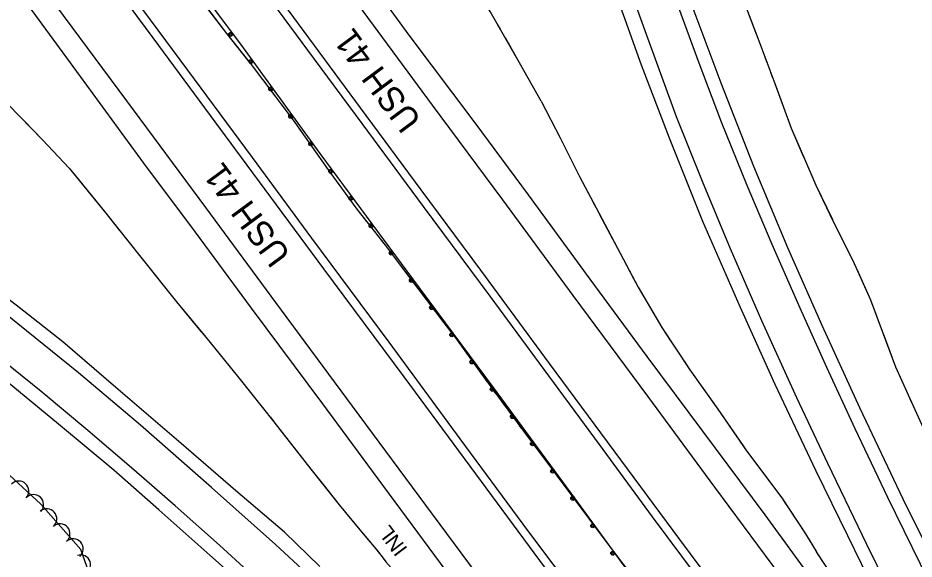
# Model space of a CAD drawing. Extents: x 353423 to 364002, y 127000 to 201942.
# Drawn here: x 359462 to 359820.6, y 132026.4 to 132242.7 of the extents above; entities that cross this region are included whole.
import ezdxf

# ---------------------------------------------------------------- set-up
doc = ezdxf.new("R2010")
doc.units = 0
for name, color, linetype in [('E_DTM_SlopeBottom', 7, 'Continuous'), ('E_DTM_SlopeTop', 7, 'Continuous'), ('E_FEN_Generic', 7, 'Continuous'), ('E_MISCPROP', 7, 'Continuous'), ('E_RW_IP', 7, 'Continuous'), ('E_STRUCT_WingWall', 7, 'Continuous')]:
    doc.layers.add(name, color=color, linetype=linetype)

msp = doc.modelspace()

# ---------------------------------------------------------------- linework, layer by layer
at = {"layer": 'E_DTM_SlopeTop'}
for points in [[(359296.04, 132656.2), (359327.36, 132613.62), (359357.21, 132573.34), (359387.83, 132532.04), (359420.96, 132487.16), (359453.44, 132443.29), (359480.05, 132407.27), (359517.09, 132357.33), (359543.42, 132321.88), (359571.35, 132284.17), (359599.99, 132245.46), (359627.75, 132207.82), (359655.85, 132169.95), (359684.1, 132131.8), (359713.89, 132091.57), (359740.72, 132055.1), (359769.42, 132016.5), (359798.55, 131977.39), (359823.57, 131943.56), (359849.91, 131908.1), (359879.42, 131867.94), (359910.1, 131826.75), (359934.24, 131793.99), (359949.98, 131772.5)], [(359894.52, 131723.73), (359866.32, 131761.93), (359834.77, 131804.35), (359801.8, 131849.06), (359771.18, 131890.36), (359741.61, 131930.36), (359706.83, 131977.37), (359677.25, 132017.15), (359645.21, 132060.41), (359616.57, 132099.29), (359584.47, 132142.49), (359551.44, 132186.98), (359516.16, 132234.78), (359477.26, 132287.18), (359438.91, 132339.08), (359394.26, 132399.62), (359356.73, 132450.28), (359318.1, 132502.23), (359283.37, 132549.19), (359243.7, 132602.83), (359207.65, 132651.41)], [(359559.38, 132644.69), (359570.47, 132614.62), (359581.22, 132584.68), (359594.59, 132548.52), (359605.61, 132517.85), (359617.82, 132483.54), (359630.69, 132448.17), (359643.78, 132412.18), (359657.78, 132373.3), (359671.34, 132335.47), (359684.05, 132300.55), (359697.66, 132262.49), (359711.33, 132223.94), (359722.6, 132194.77), (359735.93, 132161.45), (359750.82, 132127.4), (359764.9, 132096.36), (359781.29, 132061.61), (359793.98, 132035.76), (359804.87, 132013.44), (359813.81, 131995.59), (359819.82, 131983.66)], [(359449.12, 132409.2), (359470.8, 132379.85), (359494.5, 132347.87), (359517.49, 132316.9), (359547.17, 132276.9), (359572.24, 132242.9), (359598.91, 132206.77), (359623.16, 132174.01), (359647.03, 132141.86), (359674.62, 132104.55), (359700.41, 132069.65), (359726.69, 132034.19), (359755.34, 131995.76), (359785.73, 131954.75), (359813.39, 131917.61), (359840.54, 131880.58), (359870.11, 131840.52), (359899.85, 131800.63), (359928.33, 131761.92), (359958.37, 131721.52)], [(359458.15, 132391.51), (359482.94, 132357.62), (359509.06, 132322.72), (359533.32, 132290.35), (359554.33, 132261.68), (359577.87, 132229.81), (359599.59, 132200.53), (359624.12, 132167.31), (359650.84, 132131.46), (359672.46, 132102.12), (359694.57, 132072.22), (359715.85, 132043.32), (359739.28, 132011.9), (359764.96, 131977.01), (359794.26, 131937.73), (359816.26, 131908), (359839.86, 131876.35), (359866.08, 131840.78), (359888.69, 131810.32), (359912.39, 131778), (359933.4, 131749.61), (359953.69, 131722.15)], [(359898.92, 131723.42), (359872.8, 131758.76), (359846.3, 131794.45), (359818.43, 131832.09), (359795, 131863.74), (359772.17, 131894.54), (359743.48, 131933.36), (359717.7, 131968.37), (359690.1, 132005.9), (359664.2, 132040.3), (359638.9, 132074.46), (359610.49, 132113.12), (359579.6, 132154.64), (359555.84, 132186.89), (359530, 132221.9), (359503.11, 132258.09), (359475.08, 132296.24), (359444.41, 132337.76)], [(359868.2, 131719.43), (359847.41, 131747.54), (359825.57, 131776.88), (359796.6, 131815.87), (359765.6, 131857.67), (359742.12, 131889.93), (359715.95, 131925.49), (359687.37, 131963.93), (359656.97, 132005.11), (359627.89, 132044.33), (359595.85, 132087.53), (359565.18, 132128.99), (359537.2, 132166.91), (359505.6, 132209.55), (359474.16, 132252.13), (359447.44, 132288.27)], [(359751.37, 131861.94), (359744.68, 131871.36), (359730.53, 131890.77), (359712.31, 131914.84), (359693.49, 131940.26), (359673.57, 131967.47), (359649.21, 132000.18), (359628.86, 132027.78), (359606.09, 132058.41), (359583.98, 132088.43), (359555.5, 132126.69), (359533.12, 132157.04), (359512.43, 132184.65), (359487.03, 132219.32), (359462.18, 132253.26), (359440.56, 132282.21)], [(359700.05, 132273.28), (359712.8, 132237.69), (359725.4, 132203.32), (359735.76, 132177.49), (359746.99, 132150.6), (359759.54, 132121.8), (359773.57, 132090.93), (359785.92, 132064.69), (359801.61, 132032.3), (359818.33, 131998.22), (359835.34, 131964.98), (359852.8, 131932.45), (359870.66, 131900.2), (359890.88, 131865.53), (359910.85, 131832.76), (359932.41, 131798.96), (359949.98, 131772.5)], [(359592.85, 132271.02), (359618.41, 132235.79), (359644.81, 132200.77), (359666.15, 132171.99), (359690.78, 132138.33), (359713.66, 132107.36), (359735.88, 132077.57), (359760.85, 132044.13), (359785.15, 132010.81), (359805.83, 131982.59), (359812.81, 131973.72), (359817.2, 131968.39), (359819.47, 131967.02), (359821.81, 131966.89), (359824.21, 131967.81), (359825.22, 131968.91), (359825.69, 131970.63), (359825.49, 131972.75), (359823.63, 131976.39), (359819.82, 131983.66)], [(359723.98, 132253.55), (359734.47, 132224.72), (359743.46, 132201.25), (359753.66, 132175.87), (359763.64, 132152.33), (359774.89, 132126.88), (359785.49, 132103.17), (359796.86, 132078.56), (359809.93, 132051.09), (359823, 132024.51), (359835.91, 131998.55), (359850.36, 131970.51), (359864.45, 131944.59), (359881.37, 131914.12), (359896.89, 131886.8), (359916.63, 131853.64), (359931.02, 131830.55), (359947.83, 131804.43), (359966.72, 131776.07), (359988.15, 131744.83), (360003.08, 131723.98)], [(359730.51, 132251.03), (359743.22, 132216.83), (359756.28, 132183.41), (359769.95, 132150.92), (359783.7, 132119.94), (359798.77, 132086.94), (359816.13, 132050.52), (359832.64, 132017.17), (359847.63, 131987.57), (359864.22, 131956.33), (359878.9, 131929.35), (359895.89, 131899.11), (359911.69, 131872.44), (359925.25, 131849.7), (359940.63, 131825.32), (359955.08, 131803.02), (359974.09, 131774.93), (359990.7, 131750.65), (360009.57, 131723.99)], [(359582.84, 132023.49), (359568.62, 132037.16), (359549.04, 132053.79), (359527.31, 132072.56), (359501.23, 132094.99), (359479.94, 132113.2), (359462.44, 132126.97), (359442.12, 132142.6)], [(359848.21, 131724.01), (359828.93, 131748.59), (359812.62, 131768.97), (359793.78, 131792.21), (359774.6, 131815.52), (359754.43, 131839.17), (359744.04, 131851.3), (359727.16, 131870.29), (359705.92, 131893.68), (359681.76, 131919.04), (359656.38, 131945.02), (359634.73, 131966.57), (359610.44, 131989.93), (359588.34, 132010.76), (359565.03, 132032.22), (359539.45, 132055.04), (359511.05, 132079.94), (359486.28, 132100.8), (359462, 132120.43), (359439.65, 132138.15)], [(359829.79, 131722.95), (359815.52, 131741.24), (359796.41, 131765.22), (359779.05, 131786.77), (359761.9, 131807.33), (359743.27, 131829.13), (359722.54, 131852.67), (359704.55, 131872.62), (359689.86, 131888.7), (359672.14, 131907.09), (359654.35, 131925.48), (359637.61, 131942.19), (359622.74, 131956.82), (359604.84, 131974.1), (359580.59, 131997.01), (359560.31, 132015.88), (359542.62, 132031.93), (359524.86, 132047.65), (359508.32, 132062.07), (359490.01, 132077.74), (359471.36, 132093.36), (359448.96, 132111.3)], [(359818.68, 131728.32), (359802.2, 131749.43), (359778.26, 131779.18), (359757.21, 131804.4), (359732.64, 131833.16), (359709.98, 131858.45), (359689.67, 131880.76), (359671.68, 131899.94), (359652.35, 131919.4), (359633.96, 131938.19), (359612.26, 131959.63), (359593.97, 131977.08), (359573.75, 131996.16), (359555.51, 132013.17), (359538.8, 132027.98), (359518.4, 132046.12), (359500.31, 132061.96), (359478.3, 132080.28), (359457.67, 132097.26)]]:
    msp.add_lwpolyline(points, dxfattribs=at)
at = {"layer": 'E_FEN_Generic'}
msp.add_lwpolyline([(359459.55, 131994.61), (359475.13, 131986.14), (359486.17, 131985.76), (359500.76, 131980.98), (359515.71, 131969.18), (359527.78, 131960.83), (359543.14, 131955.44), (359549.13, 131963.42), (359544.07, 131986.86), (359537.29, 132001.06), (359524.78, 132008.3), (359506.54, 132008.49), (359492.06, 132016.18), (359487.16, 132030.2), (359471.17, 132048.35), (359458.45, 132060.05)], dxfattribs=at)
for centre, start, end in [((359462.38, 132053.59), 317.4069, 137.3916), ((359468.27, 132048.17), 317.4069, 137.3916), ((359473.56, 132042.48), 311.3813, 131.366), ((359478.84, 132036.47), 311.3813, 131.366), ((359484.13, 132030.47), 311.3813, 131.366), ((359487.1, 132024.04), 289.2925, 109.2772)]:
    msp.add_arc(centre, 4, start, end, dxfattribs=at)
at = {"layer": 'E_MISCPROP'}
msp.add_lwpolyline([(359794.82, 131895.17), (359785.88, 131912.02), (359777.23, 131925.64), (359764.95, 131943.08), (359744.59, 131970.35), (359715.45, 132008.96), (359684.89, 132050.81), (359652.25, 132094.96), (359619.98, 132138.39), (359582.9, 132188.54), (359551.14, 132232.24), (359516.07, 132278.98), (359488.15, 132316.91), (359461.53, 132352.04), (359435.69, 132387.15), (359404.53, 132429.46), (359381.64, 132459.87), (359354.43, 132496.95), (359323.55, 132538.97), (359304.01, 132565.28), (359269, 132611.91), (359258.9, 132624.99)], dxfattribs=at)
msp.add_lwpolyline([(359794.82, 131895.17), (359785.88, 131912.02), (359777.23, 131925.64), (359764.95, 131943.08), (359744.59, 131970.35), (359715.45, 132008.96), (359684.89, 132050.81), (359652.25, 132094.96), (359619.98, 132138.39), (359582.9, 132188.54), (359551.14, 132232.24), (359516.07, 132278.98), (359488.15, 132316.91), (359461.53, 132352.04), (359435.69, 132387.15), (359404.53, 132429.46), (359381.64, 132459.87), (359354.43, 132496.95), (359323.55, 132538.97), (359304.01, 132565.28), (359269, 132611.91), (359258.9, 132624.99)], dxfattribs=at)
for centre, radius in [((359547.17, 132236.21), 0.79), ((359547.14, 132236.25), 0.398), ((359555.2, 132225.3), 0.79), ((359555.18, 132225.34), 0.398), ((359563.18, 132214.33), 0.79), ((359563.15, 132214.37), 0.398), ((359571.15, 132203.36), 0.79), ((359571.13, 132203.4), 0.398), ((359579.13, 132192.39), 0.79), ((359579.1, 132192.42), 0.398), ((359587.16, 132181.45), 0.79), ((359587.13, 132181.49), 0.398), ((359595.22, 132170.55), 0.79), ((359595.2, 132170.58), 0.398), ((359603.29, 132159.64), 0.79), ((359603.26, 132159.68), 0.398), ((359611.35, 132148.74), 0.79), ((359611.32, 132148.77), 0.398), ((359619.42, 132137.83), 0.79), ((359619.39, 132137.86), 0.398), ((359627.5, 132126.94), 0.79), ((359627.48, 132126.98), 0.398), ((359635.59, 132116.05), 0.79), ((359635.57, 132116.09), 0.398), ((359643.68, 132105.17), 0.79), ((359643.66, 132105.2), 0.398), ((359651.77, 132094.28), 0.79), ((359651.74, 132094.32), 0.398), ((359659.83, 132083.37), 0.79), ((359659.81, 132083.41), 0.398), ((359667.89, 132072.47), 0.79), ((359667.87, 132072.5), 0.398), ((359675.96, 132061.56), 0.79), ((359675.93, 132061.6), 0.398), ((359684.02, 132050.66), 0.79), ((359684, 132050.69), 0.398), ((359692.02, 132039.71), 0.79), ((359691.99, 132039.74), 0.398), ((359700.02, 132028.75), 0.79), ((359699.99, 132028.79), 0.398)]:
    msp.add_circle(centre, radius, dxfattribs=at)
at = {"layer": 'E_STRUCT_WingWall'}
for points in [[(359671.35, 132209.49), (359662.72, 132224.78), (359650.97, 132245.33), (359640.24, 132262.54), (359628.86, 132280.41), (359619.71, 132294.43), (359610.23, 132308.61), (359601.09, 132322.57), (359591.51, 132337.31), (359582.18, 132350.32), (359572.48, 132363.73), (359564.2, 132376.06), (359555.48, 132387.68), (359546.97, 132398.9), (359540.92, 132405.59), (359532.33, 132414.7), (359524.95, 132421.51), (359518.17, 132427.93), (359512.82, 132432.27), (359510.06, 132434.3), (359506.95, 132435.12)], [(359747.2, 132263.13), (359751.74, 132251.13), (359757.53, 132236.03)], [(359533.84, 132251.7), (359545.42, 132236.49), (359554.93, 132224.59), (359565.25, 132211.06), (359572.76, 132200.91), (359586.14, 132181.95), (359597.22, 132166.75), (359608.97, 132151.82), (359622.04, 132134.59), (359637.07, 132114.84), (359650.51, 132096.16), (359663.57, 132078.43), (359675.48, 132062.55), (359684.04, 132051.1), (359696.93, 132033.88), (359707.8, 132019.51)], [(359751.74, 132251.13), (359758.08, 132234.58), (359764.84, 132216.53), (359771.44, 132198.65), (359776.71, 132186.46), (359781.22, 132175.84), (359788.35, 132161.12), (359796.09, 132145.73), (359803.16, 132130.07), (359808.19, 132116.49), (359813.17, 132103.19), (359818.22, 132092.06), (359824.86, 132077.41)], [(359536.2, 132248.6), (359545.42, 132236.49), (359554.02, 132225.72)], [(359655.05, 132238.19), (359654.06, 132239.93)], [(359426.12, 132234.57), (359436.9, 132227.89), (359446.54, 132218.99), (359458.12, 132208.07), (359471.88, 132194.01), (359482.56, 132182.7), (359497.11, 132164.74), (359511.23, 132147.05), (359525.51, 132129.2), (359537.21, 132115.05), (359550.4, 132098.88), (359564.4, 132081.31), (359579.23, 132062.33), (359590.6, 132048.13), (359598.18, 132038.87), (359604.56, 132031.28), (359607.74, 132027.35), (359609.28, 132025.33), (359611.31, 132022.92)], [(359671.35, 132209.49), (359662.72, 132224.78), (359657.04, 132234.72)], [(359758.94, 132232.29), (359759.64, 132230.42)], [(359761.04, 132226.67), (359761.75, 132224.8)], [(359556.47, 132222.56), (359557.69, 132220.97)], [(359763.15, 132221.05), (359763.85, 132219.18)], [(359560.11, 132217.79), (359561.33, 132216.2)], [(359765.25, 132215.43), (359771.44, 132198.65), (359775.85, 132188.45)], [(359563.75, 132213.02), (359564.97, 132211.43)], [(359567.35, 132208.22), (359572.76, 132200.91), (359584.24, 132184.64)], [(359671.35, 132209.49), (359679.04, 132194.77), (359686.66, 132179.33), (359694.41, 132164.77), (359702.92, 132148.65), (359710.12, 132135.16), (359719.64, 132118.98), (359730.86, 132102.05), (359742.1, 132086.29), (359753.56, 132069.63), (359767.61, 132050.83), (359777.19, 132036.43), (359781.51, 132029.26)], [(359671.35, 132209.49), (359679.04, 132194.77), (359684.52, 132183.66)], [(359464.61, 132201.44), (359471.88, 132194.01), (359482.56, 132182.7), (359484.48, 132180.33)], [(359775.85, 132188.45), (359776.71, 132186.46), (359781.22, 132175.84), (359787.89, 132162.08)], [(359584.24, 132184.64), (359586.14, 132181.95), (359597.22, 132166.75), (359601.48, 132161.33)], [(359484.48, 132180.33), (359497.11, 132164.74), (359502.69, 132157.76)], [(359686.29, 132180.08), (359686.66, 132179.33), (359687.21, 132178.3)], [(359689.09, 132174.77), (359690.03, 132173)], [(359691.91, 132169.47), (359692.85, 132167.71)], [(359694.73, 132164.17), (359702.92, 132148.65), (359708.31, 132138.55)], [(359603.96, 132158.19), (359605.19, 132156.62)], [(359789.67, 132158.5), (359790.57, 132156.71)], [(359505.18, 132154.63), (359506.43, 132153.07)], [(359607.67, 132153.48), (359608.9, 132151.9)], [(359792.37, 132153.14), (359793.27, 132151.35)], [(359508.92, 132149.94), (359510.17, 132148.38)], [(359611.32, 132148.72), (359612.53, 132147.12)], [(359795.06, 132147.77), (359795.96, 132145.99)], [(359512.67, 132145.25), (359513.92, 132143.69)], [(359614.95, 132143.94), (359622.04, 132134.59), (359632.49, 132120.85)], [(359797.62, 132142.35), (359803.16, 132130.07), (359808.19, 132116.49), (359808.56, 132115.51)], [(359516.42, 132140.57), (359525.51, 132129.2), (359534.72, 132118.07)], [(359708.31, 132138.55), (359710.12, 132135.16), (359719.64, 132118.98), (359723.16, 132113.66)], [(359632.49, 132120.85), (359637.07, 132114.84), (359649.6, 132097.43)], [(359534.72, 132118.07), (359537.21, 132115.05), (359550.4, 132098.88), (359553.03, 132095.58)], [(359808.56, 132115.51), (359813.17, 132103.19), (359818.22, 132092.06), (359819.72, 132088.76)], [(359725.37, 132110.32), (359726.48, 132108.66)], [(359728.69, 132105.32), (359729.79, 132103.66)], [(359732.06, 132100.36), (359733.23, 132098.74)], [(359735.55, 132095.48), (359742.1, 132086.29), (359752.14, 132071.7)], [(359555.52, 132092.46), (359556.77, 132090.89)], [(359651.95, 132094.2), (359653.14, 132092.59)], [(359655.51, 132089.37), (359656.7, 132087.76)], [(359559.26, 132087.76), (359560.51, 132086.2)], [(359563, 132083.07), (359564.24, 132081.51)], [(359659.07, 132084.54), (359660.26, 132082.93)], [(359566.71, 132078.36), (359579.23, 132062.33), (359584.65, 132055.57)], [(359662.63, 132079.71), (359663.57, 132078.43), (359675.48, 132062.55), (359680.01, 132056.49)], [(359752.14, 132071.7), (359753.56, 132069.63), (359767.61, 132050.83), (359769.29, 132048.31)], [(359680.01, 132056.49), (359684.04, 132051.1), (359696.93, 132033.88), (359697.39, 132033.28)], [(359584.65, 132055.57), (359590.6, 132048.13), (359598.18, 132038.87), (359603.01, 132033.12)], [(359771.5, 132044.98), (359772.61, 132043.32)], [(359774.82, 132039.99), (359775.93, 132038.32)], [(359778.08, 132034.95), (359779.11, 132033.24)], [(359605.56, 132030.05), (359606.82, 132028.49)], [(359699.8, 132030.08), (359701.01, 132028.49)], [(359781.18, 132029.81), (359781.51, 132029.26)], [(359799.79, 131999.84), (359794.88, 132008.96), (359789.02, 132017.99), (359781.51, 132029.26)], [(359782.43, 132027.88), (359781.51, 132029.26)]]:
    msp.add_lwpolyline(points, dxfattribs=at)

# ---------------------------------------------------------------- texts
at = {"layer": 'E_DTM_SlopeBottom'}
msp.add_text('INL', height=6, rotation=127.1174, dxfattribs=at).set_placement((359618.14, 132030.52))
at = {"layer": 'E_RW_IP'}
for rotation, p in [(126.5675, (359623.86, 132201.75)), (126.4188, (359571.54, 132148.03))]:
    msp.add_text('USH 41', height=10, rotation=rotation, dxfattribs=at).set_placement(p)

doc.saveas('drawing.dxf')
